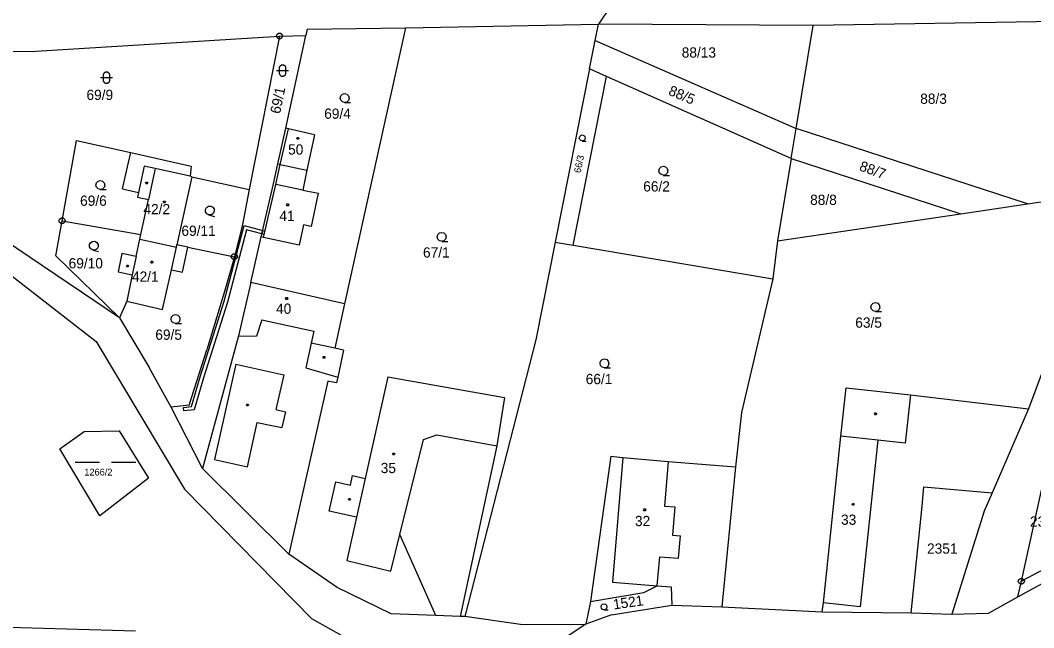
# Model space of a CAD drawing. Extents: x -852001 to -848657, y -1054973 to -1052182.
# Drawn here: x -850781 to -850612.8, y -1053430.4 to -1053329.6 of the extents above; entities that cross this region are included whole.
import ezdxf

# ---------------------------------------------------------------- set-up
doc = ezdxf.new("R2010")
doc.units = 0
for name, color, linetype in [('KN_BREMENA', 7, 'Continuous'), ('KN_HRANICE', 7, 'Continuous'), ('KN_KULTURY', 7, 'Continuous'), ('KN_MEZNIKY', 7, 'Continuous'), ('KN_PARCELY', 7, 'Continuous'), ('KN_SLUCKY', 7, 'Continuous'), ('KN_STAVEBNI', 7, 'Continuous')]:
    doc.layers.add(name, color=color, linetype=linetype)

# ---------------------------------------------------------------- blocks, each defined once
blk = doc.blocks.new('304')
blk.add_lwpolyline([(0, 0), (-0.38, 0.1), (-0.65, 0.37), (-0.75, 0.74), (-0.65, 1.11), (-0.38, 1.38), (-0.01, 1.48), (0.36, 1.38), (0.63, 1.11), (0.73, 0.73), (0.63, 0.35), (0.36, 0.08), (-0.02, -0.02), (0.98, -0.02)])
blk = doc.blocks.new('316')
for points in [[(-0.5, 1.5), (-0.4, 1.79), (-0.15, 1.97), (0.16, 1.97), (0.41, 1.79), (0.51, 1.5), (0.51, 0.5), (0.41, 0.21), (0.16, 0.03), (-0.15, 0.03), (-0.4, 0.21), (-0.5, 0.5), (-0.5, 1.5)], [(-1, 1), (0.27, 1), (1, 1)]]:
    blk.add_lwpolyline(points)
blk = doc.blocks.new('803')
for p, q in [((-7.5, 0), (-1.5, 0)), ((1.5, 0), (7.5, 0))]:
    blk.add_line(p, q)
blk = doc.blocks.new('402')
blk.add_lwpolyline([(0.09, 0.15), (0.18, 0), (0.09, -0.15), (-0.09, -0.15), (-0.18, 0), (-0.09, 0.15), (0.09, 0.15)])
blk = doc.blocks.new('105')
blk.add_line((-0.12, 0), (0.12, 0))
blk.add_lwpolyline([(0.15, 0.48), (0.4, 0.3), (0.5, 0.01), (0.4, -0.28), (0.15, -0.46), (-0.16, -0.46), (-0.41, -0.28), (-0.51, 0.01), (-0.41, 0.3), (-0.16, 0.48), (0.15, 0.48)])

msp = doc.modelspace()

# ---------------------------------------------------------------- linework, layer by layer
at = {"layer": 'KN_BREMENA'}
for p, q in [((-850743.82, -1053363.69), (-850740.72, -1053364.49)), ((-850740.72, -1053364.49), (-850740.85, -1053365.06))]:
    msp.add_line(p, q, dxfattribs=at)
msp.add_lwpolyline([(-850740.85, -1053365.06), (-850743.4, -1053364.41), (-850746.54, -1053376.39), (-850750.55, -1053388.95), (-850752.08, -1053394.24), (-850753.79, -1053394.45), (-850753.86, -1053393.86), (-850752.54, -1053393.7), (-850751.13, -1053388.77), (-850747.12, -1053376.23), (-850743.82, -1053363.69)], dxfattribs=at)
msp.add_lwpolyline([(-850740.72, -1053364.49), (-850740.39, -1053364.57), (-850740.52, -1053365.15), (-850740.85, -1053365.06)], close=True, dxfattribs=at)
at = {"layer": 'KN_HRANICE'}
for p, q in [((-850683.07, -1053327.37), (-850685.02, -1053330.25)), ((-850717.05, -1053330.88), (-850685.02, -1053330.25)), ((-850685.56, -1053333), (-850685.02, -1053330.25)), ((-850649.35, -1053330.52), (-850685.02, -1053330.25)), ((-850652.19, -1053347.57), (-850649.35, -1053330.52)), ((-850605.07, -1053329.74), (-850649.35, -1053330.52)), ((-850778.4, -1053334.78), (-850737.94, -1053332.24)), ((-850737.94, -1053332.24), (-850742.99, -1053357.7)), ((-850737.94, -1053332.24), (-850733.55, -1053332.18)), ((-850736.86, -1053347.53), (-850733.55, -1053332.18)), ((-850733.34, -1053331.11), (-850733.55, -1053332.18)), ((-850733.34, -1053331.11), (-850717.05, -1053330.88)), ((-850717.05, -1053330.88), (-850727.14, -1053376.69)), ((-850686.5, -1053337.71), (-850685.56, -1053333)), ((-850685.56, -1053333), (-850652.19, -1053347.57)), ((-850815.48, -1053335.08), (-850778.4, -1053334.78)), ((-850686.5, -1053337.71), (-850692.17, -1053366.45)), ((-850689.22, -1053366.95), (-850683.69, -1053338.94)), ((-850683.69, -1053338.94), (-850686.5, -1053337.71)), ((-850653.03, -1053352.56), (-850683.69, -1053338.94)), ((-850738.2, -1053353.47), (-850736.86, -1053347.53)), ((-850736.47, -1053347.62), (-850736.86, -1053347.53)), ((-850732.12, -1053348.62), (-850736.47, -1053347.62)), ((-850732.12, -1053348.62), (-850733.38, -1053354.52)), ((-850653.03, -1053352.56), (-850652.19, -1053347.57)), ((-850613.8, -1053360.1), (-850652.19, -1053347.57)), ((-850774.01, -1053362.91), (-850771.62, -1053349.55)), ((-850771.62, -1053349.55), (-850762.61, -1053351.58)), ((-850762.99, -1053353.25), (-850762.61, -1053351.58)), ((-850762.61, -1053351.58), (-850752.61, -1053353.83)), ((-850653.03, -1053352.56), (-850655.32, -1053366.23)), ((-850653.03, -1053352.56), (-850624.89, -1053361.75)), ((-850763.97, -1053357.61), (-850762.99, -1053353.25)), ((-850752.61, -1053353.83), (-850752.76, -1053355.52)), ((-850738.94, -1053356.76), (-850738.2, -1053353.47)), ((-850738.2, -1053353.47), (-850737.81, -1053353.56)), ((-850737.81, -1053353.56), (-850733.38, -1053354.52)), ((-850752.51, -1053355.58), (-850754.95, -1053366.89)), ((-850752.51, -1053355.58), (-850752.76, -1053355.52)), ((-850752.51, -1053355.58), (-850742.99, -1053357.7)), ((-850733.38, -1053354.52), (-850734.08, -1053357.8)), ((-850763.97, -1053357.61), (-850761.34, -1053358.18)), ((-850740.97, -1053365.57), (-850738.94, -1053356.76)), ((-850761.34, -1053358.18), (-850761.52, -1053358.99)), ((-850761.52, -1053358.99), (-850759.68, -1053359.39)), ((-850742.99, -1053357.7), (-850744.07, -1053363.49)), ((-850734.08, -1053357.8), (-850731.54, -1053358.34)), ((-850731.54, -1053358.34), (-850732.71, -1053363.82)), ((-850613.8, -1053360.1), (-850606.19, -1053358.98)), ((-850760.97, -1053365.18), (-850759.68, -1053359.39)), ((-850624.89, -1053361.75), (-850613.8, -1053360.1)), ((-850655.32, -1053366.23), (-850624.89, -1053361.75)), ((-850775.07, -1053368.7), (-850774.01, -1053362.91)), ((-850774.01, -1053362.91), (-850760.97, -1053365.18)), ((-850744.07, -1053363.49), (-850745.43, -1053368.86)), ((-850733.94, -1053363.56), (-850734.66, -1053366.93)), ((-850732.71, -1053363.82), (-850733.94, -1053363.56)), ((-850761.73, -1053368.82), (-850761.14, -1053365.96)), ((-850761.14, -1053365.96), (-850760.97, -1053365.18)), ((-850761.14, -1053365.96), (-850755.03, -1053367.28)), ((-850742.71, -1053373.12), (-850740.97, -1053365.57)), ((-850740.58, -1053365.66), (-850740.97, -1053365.57)), ((-850734.66, -1053366.93), (-850740.58, -1053365.66)), ((-850764.51, -1053379), (-850783.59, -1053366.1)), ((-850755.03, -1053367.28), (-850754.95, -1053366.89)), ((-850753.13, -1053367.26), (-850754.95, -1053366.89)), ((-850754.04, -1053371.43), (-850753.13, -1053367.26)), ((-850753.13, -1053367.26), (-850745.43, -1053368.86)), ((-850692.17, -1053366.45), (-850695.38, -1053382.66)), ((-850692.17, -1053366.45), (-850689.22, -1053366.95)), ((-850689.22, -1053366.95), (-850656.06, -1053372.51)), ((-850655.32, -1053366.23), (-850656.06, -1053372.51)), ((-850775.07, -1053368.7), (-850764.51, -1053379)), ((-850764.08, -1053368.33), (-850764.71, -1053371.37)), ((-850761.73, -1053368.82), (-850764.08, -1053368.33)), ((-850745.43, -1053368.86), (-850746.88, -1053374.1)), ((-850783.8, -1053370.9), (-850768.38, -1053382.92)), ((-850757.36, -1053377.59), (-850755.86, -1053371.06)), ((-850755.86, -1053371.06), (-850754.04, -1053371.43)), ((-850764.71, -1053371.37), (-850762.36, -1053371.85)), ((-850762.36, -1053371.85), (-850763.28, -1053376.26)), ((-850656.06, -1053372.51), (-850661.28, -1053394.73)), ((-850746.88, -1053374.1), (-850750, -1053384.28)), ((-850742.71, -1053373.12), (-850744.73, -1053381.99)), ((-850727.14, -1053376.69), (-850742.71, -1053373.12)), ((-850763.28, -1053376.26), (-850764.51, -1053379)), ((-850763.28, -1053376.26), (-850757.36, -1053377.59)), ((-850727.14, -1053376.69), (-850728.76, -1053384.05)), ((-850764.51, -1053379), (-850759.56, -1053387.26)), ((-850744.73, -1053381.99), (-850750.73, -1053404.02)), ((-850695.38, -1053382.66), (-850707.19, -1053428.56)), ((-850608.91, -1053381.35), (-850613.67, -1053394.11)), ((-850768.38, -1053382.92), (-850753.68, -1053407.41)), ((-850752.92, -1053393.49), (-850750, -1053384.28)), ((-850727.29, -1053384.37), (-850728.76, -1053384.05)), ((-850727.29, -1053384.37), (-850728.26, -1053388.82)), ((-850755.92, -1053393.81), (-850759.56, -1053387.26)), ((-850729.91, -1053389.48), (-850736.41, -1053418.2)), ((-850728.47, -1053389.8), (-850729.91, -1053389.48)), ((-850728.26, -1053388.82), (-850728.47, -1053389.8)), ((-850719.96, -1053388.76), (-850723.72, -1053405.65)), ((-850719.96, -1053388.76), (-850700.61, -1053392.2)), ((-850644.8, -1053398.62), (-850643.92, -1053390.61)), ((-850643.92, -1053390.61), (-850633.21, -1053391.79)), ((-850700.61, -1053392.2), (-850701.86, -1053400.23)), ((-850633.21, -1053391.79), (-850613.67, -1053394.11)), ((-850752.92, -1053393.49), (-850755.92, -1053393.81)), ((-850750.73, -1053404.02), (-850755.92, -1053393.81)), ((-850613.67, -1053394.11), (-850619.67, -1053408.02)), ((-850661.28, -1053394.73), (-850662.28, -1053403.7)), ((-850774.4, -1053400.72), (-850770.36, -1053397.87)), ((-850770.36, -1053397.87), (-850764.52, -1053397.77)), ((-850764.52, -1053397.77), (-850759.66, -1053405.62)), ((-850647.64, -1053426.28), (-850644.8, -1053398.62)), ((-850767.78, -1053411.85), (-850774.4, -1053400.72)), ((-850701.86, -1053400.23), (-850707.94, -1053428.53)), ((-850614.83, -1053422.71), (-850610.11, -1053401.34)), ((-850682.94, -1053401.97), (-850686.34, -1053426.05)), ((-850682.94, -1053401.97), (-850680.99, -1053402.15)), ((-850680.99, -1053402.15), (-850673.43, -1053402.82)), ((-850673.43, -1053402.82), (-850662.28, -1053403.7)), ((-850736.41, -1053418.2), (-850750.73, -1053404.02)), ((-850662.28, -1053403.7), (-850664.55, -1053426.95)), ((-850759.66, -1053405.62), (-850767.78, -1053411.85)), ((-850729.69, -1053411.08), (-850728.61, -1053406.2)), ((-850728.61, -1053406.2), (-850726.16, -1053406.74)), ((-850726.16, -1053406.74), (-850725.82, -1053405.18)), ((-850725.82, -1053405.18), (-850723.72, -1053405.65)), ((-850732.58, -1053428.94), (-850753.68, -1053407.41)), ((-850631.28, -1053410.23), (-850631.01, -1053407.05)), ((-850631.01, -1053407.05), (-850619.67, -1053408.02)), ((-850619.67, -1053408.02), (-850621, -1053411.06)), ((-850725.15, -1053412.09), (-850729.69, -1053411.08)), ((-850633.09, -1053427.94), (-850631.28, -1053410.23)), ((-850621, -1053411.06), (-850626.39, -1053428.15)), ((-850725.15, -1053412.09), (-850726.75, -1053419.27)), ((-850599.75, -1053414.73), (-850614.83, -1053422.71)), ((-850719.44, -1053421.05), (-850717.98, -1053414.96)), ((-850712, -1053428.38), (-850717.98, -1053414.96)), ((-850615.4, -1053425.29), (-850599.94, -1053416.73)), ((-850728.38, -1053423.75), (-850736.41, -1053418.2)), ((-850726.75, -1053419.27), (-850719.44, -1053421.05)), ((-850615.4, -1053425.29), (-850614.83, -1053422.71)), ((-850719.41, -1053428.11), (-850728.38, -1053423.75)), ((-850686.34, -1053426.05), (-850677.49, -1053424.55)), ((-850677.49, -1053424.55), (-850675.24, -1053423.48)), ((-850675.24, -1053423.48), (-850672.94, -1053423.65)), ((-850672.94, -1053423.65), (-850672.81, -1053426.68)), ((-850686.34, -1053426.05), (-850687.09, -1053429.83)), ((-850647.86, -1053427.79), (-850647.64, -1053426.28)), ((-850620.26, -1053427.98), (-850615.4, -1053425.29)), ((-850712, -1053428.38), (-850719.41, -1053428.11)), ((-850682.84, -1053428.25), (-850687.09, -1053429.83)), ((-850682.84, -1053428.25), (-850672.81, -1053426.68)), ((-850672.81, -1053426.68), (-850664.55, -1053426.95)), ((-850664.55, -1053426.95), (-850647.86, -1053427.79)), ((-850647.86, -1053427.79), (-850633.09, -1053427.94)), ((-850633.09, -1053427.94), (-850626.39, -1053428.15)), ((-850626.39, -1053428.15), (-850620.26, -1053427.98)), ((-850800.29, -1053429.81), (-850761.82, -1053430.94)), ((-850721.08, -1053435.35), (-850732.58, -1053428.94)), ((-850707.94, -1053428.53), (-850712, -1053428.38)), ((-850707.19, -1053428.56), (-850707.94, -1053428.53)), ((-850697.93, -1053429.89), (-850707.19, -1053428.56)), ((-850697.93, -1053429.89), (-850687.09, -1053429.83)), ((-850687.09, -1053429.83), (-850693.44, -1053434))]:
    msp.add_line(p, q, dxfattribs=at)
at = {"layer": 'KN_SLUCKY'}
for p, q in [((-850737.81, -1053353.56), (-850736.47, -1053347.62)), ((-850760.4, -1053353.83), (-850761.34, -1053358.18)), ((-850758.56, -1053354.23), (-850760.4, -1053353.83)), ((-850758.56, -1053354.23), (-850759.68, -1053359.39)), ((-850752.76, -1053355.52), (-850758.56, -1053354.23)), ((-850738.55, -1053356.85), (-850737.81, -1053353.56)), ((-850740.58, -1053365.66), (-850738.55, -1053356.85)), ((-850734.08, -1053357.8), (-850738.55, -1053356.85)), ((-850755.86, -1053371.06), (-850755.03, -1053367.28)), ((-850761.73, -1053368.82), (-850762.36, -1053371.85)), ((-850740.86, -1053379.33), (-850741.78, -1053382.03)), ((-850740.86, -1053379.33), (-850732.23, -1053381.21)), ((-850744.73, -1053381.99), (-850741.78, -1053382.03)), ((-850732.23, -1053381.21), (-850732.66, -1053383.2)), ((-850732.66, -1053383.2), (-850733.55, -1053387.28)), ((-850728.76, -1053384.05), (-850732.66, -1053383.2)), ((-850745.21, -1053386.71), (-850748.7, -1053402.5)), ((-850745.21, -1053386.71), (-850737.24, -1053388.44)), ((-850733.55, -1053387.28), (-850728.26, -1053388.82)), ((-850737.24, -1053388.44), (-850738.57, -1053394.19)), ((-850633.21, -1053391.79), (-850634.1, -1053399.81)), ((-850738.57, -1053394.19), (-850736.94, -1053394.57)), ((-850736.94, -1053394.57), (-850737.55, -1053397.22)), ((-850743.26, -1053403.71), (-850741.63, -1053396.36)), ((-850741.63, -1053396.36), (-850739.2, -1053396.84)), ((-850739.2, -1053396.84), (-850737.55, -1053397.22)), ((-850717.98, -1053414.96), (-850714.06, -1053399.19)), ((-850714.06, -1053399.19), (-850711.85, -1053398.4)), ((-850711.85, -1053398.4), (-850701.86, -1053400.23)), ((-850638.67, -1053399.32), (-850644.8, -1053398.62)), ((-850638.67, -1053399.32), (-850641.6, -1053426.95)), ((-850634.1, -1053399.81), (-850638.67, -1053399.32)), ((-850748.7, -1053402.5), (-850743.26, -1053403.71)), ((-850680.99, -1053402.15), (-850682.67, -1053422.88)), ((-850673.43, -1053402.82), (-850674.07, -1053410.23)), ((-850723.72, -1053405.65), (-850725.15, -1053412.09)), ((-850674.07, -1053410.23), (-850672.33, -1053410.38)), ((-850672.33, -1053410.38), (-850672.74, -1053415.05)), ((-850672.74, -1053415.05), (-850671.4, -1053415.17)), ((-850671.72, -1053418.85), (-850671.4, -1053415.17)), ((-850675.24, -1053423.48), (-850674.85, -1053418.65)), ((-850674.85, -1053418.65), (-850671.72, -1053418.85)), ((-850682.67, -1053422.88), (-850675.24, -1053423.48)), ((-850641.6, -1053426.95), (-850647.64, -1053426.28))]:
    msp.add_line(p, q, dxfattribs=at)
at = {"layer": 'KN_STAVEBNI'}
for p, q in [((-850737.81, -1053353.56), (-850736.47, -1053347.62)), ((-850732.12, -1053348.62), (-850736.47, -1053347.62)), ((-850732.12, -1053348.62), (-850733.38, -1053354.52)), ((-850758.56, -1053354.23), (-850759.68, -1053359.39)), ((-850752.76, -1053355.52), (-850758.56, -1053354.23)), ((-850737.81, -1053353.56), (-850733.38, -1053354.52)), ((-850752.51, -1053355.58), (-850754.95, -1053366.89)), ((-850752.51, -1053355.58), (-850752.76, -1053355.52)), ((-850740.58, -1053365.66), (-850738.55, -1053356.85)), ((-850734.08, -1053357.8), (-850738.55, -1053356.85)), ((-850734.08, -1053357.8), (-850731.54, -1053358.34)), ((-850731.54, -1053358.34), (-850732.71, -1053363.82)), ((-850760.97, -1053365.18), (-850759.68, -1053359.39)), ((-850733.94, -1053363.56), (-850734.66, -1053366.93)), ((-850732.71, -1053363.82), (-850733.94, -1053363.56)), ((-850761.73, -1053368.82), (-850761.14, -1053365.96)), ((-850761.14, -1053365.96), (-850760.97, -1053365.18)), ((-850761.14, -1053365.96), (-850755.03, -1053367.28)), ((-850761.14, -1053365.96), (-850755.03, -1053367.28)), ((-850734.66, -1053366.93), (-850740.58, -1053365.66)), ((-850755.86, -1053371.06), (-850755.03, -1053367.28)), ((-850755.03, -1053367.28), (-850754.95, -1053366.89)), ((-850761.73, -1053368.82), (-850762.36, -1053371.85)), ((-850757.36, -1053377.59), (-850755.86, -1053371.06)), ((-850762.36, -1053371.85), (-850763.28, -1053376.26)), ((-850742.71, -1053373.12), (-850744.73, -1053381.99)), ((-850727.14, -1053376.69), (-850742.71, -1053373.12)), ((-850763.28, -1053376.26), (-850757.36, -1053377.59)), ((-850727.14, -1053376.69), (-850728.76, -1053384.05)), ((-850740.86, -1053379.33), (-850741.78, -1053382.03)), ((-850740.86, -1053379.33), (-850732.23, -1053381.21)), ((-850744.73, -1053381.99), (-850741.78, -1053382.03)), ((-850732.23, -1053381.21), (-850732.66, -1053383.2)), ((-850728.76, -1053384.05), (-850732.66, -1053383.2)), ((-850719.96, -1053388.76), (-850723.72, -1053405.65)), ((-850719.96, -1053388.76), (-850700.61, -1053392.2)), ((-850700.61, -1053392.2), (-850701.86, -1053400.23)), ((-850717.98, -1053414.96), (-850714.06, -1053399.19)), ((-850714.06, -1053399.19), (-850711.85, -1053398.4)), ((-850711.85, -1053398.4), (-850701.86, -1053400.23)), ((-850647.64, -1053426.28), (-850644.8, -1053398.62)), ((-850638.67, -1053399.32), (-850644.8, -1053398.62)), ((-850638.67, -1053399.32), (-850641.6, -1053426.95)), ((-850680.99, -1053402.15), (-850682.67, -1053422.88)), ((-850680.99, -1053402.15), (-850673.43, -1053402.82)), ((-850673.43, -1053402.82), (-850674.07, -1053410.23)), ((-850723.72, -1053405.65), (-850725.15, -1053412.09)), ((-850674.07, -1053410.23), (-850672.33, -1053410.38)), ((-850672.33, -1053410.38), (-850672.74, -1053415.05)), ((-850725.15, -1053412.09), (-850726.75, -1053419.27)), ((-850719.44, -1053421.05), (-850717.98, -1053414.96)), ((-850672.74, -1053415.05), (-850671.4, -1053415.17)), ((-850671.72, -1053418.85), (-850671.4, -1053415.17)), ((-850726.75, -1053419.27), (-850719.44, -1053421.05)), ((-850675.24, -1053423.48), (-850674.85, -1053418.65)), ((-850674.85, -1053418.65), (-850671.72, -1053418.85)), ((-850682.67, -1053422.88), (-850675.24, -1053423.48)), ((-850641.6, -1053426.95), (-850647.64, -1053426.28))]:
    msp.add_line(p, q, dxfattribs=at)

# ---------------------------------------------------------------- block references
at = {"layer": 'KN_KULTURY'}
for name, p in [('316', (-850737.43, -1053338.97)), ('316', (-850766.65, -1053340.15)), ('304', (-850727.12, -1053343.27)), ('402', (-850734.89, -1053349.21)), ('304', (-850674.22, -1053355.34)), ('304', (-850767.67, -1053357.71)), ('402', (-850759.98, -1053356.64)), ('402', (-850757.04, -1053359.79)), ('402', (-850736.58, -1053360.24)), ('304', (-850711, -1053366.3)), ('402', (-850763.15, -1053370.39)), ('402', (-850759.13, -1053369.76)), ('402', (-850736.74, -1053375.78)), ('304', (-850639.03, -1053377.94)), ('304', (-850755.19, -1053379.94)), ('402', (-850730.54, -1053385.54)), ('304', (-850684, -1053387.3)), ('402', (-850743.25, -1053393.45)), ('402', (-850639.02, -1053394.93)), ('402', (-850718.98, -1053401.6)), ('402', (-850726.33, -1053409.11)), ('402', (-850677.33, -1053410.86)), ('402', (-850642.75, -1053409.95))]:
    msp.add_blockref(name, p, dxfattribs=at)
at = {"layer": 'KN_KULTURY', "xscale": 0.67, "yscale": 0.67}
for name, p in [('304', (-850687.68, -1053349.65)), ('803', (-850766.81, -1053402.95)), ('304', (-850684.08, -1053427.44))]:
    msp.add_blockref(name, p, dxfattribs=at)
at = {"layer": 'KN_KULTURY', "rotation": -13.589717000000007}
for p in [(-850749.67, -1053361.91), (-850749.67, -1053361.91), (-850768.9, -1053367.74), (-850768.9, -1053367.74)]:
    msp.add_blockref('304', p, dxfattribs=at)
at = {"layer": 'KN_MEZNIKY'}
for p in [(-850737.94, -1053332.24), (-850774.01, -1053362.91), (-850745.43, -1053368.86), (-850614.83, -1053422.71)]:
    msp.add_blockref('105', p, dxfattribs=at)

# ---------------------------------------------------------------- texts
at = {"layer": 'KN_PARCELY'}
for s, height, p in [('88/13', 1.7, (-850671.19, -1053335.82)), ('69/9', 1.7, (-850769.97, -1053342.85)), ('88/3', 1.7, (-850631.61, -1053343.49)), ('69/4', 1.7, (-850730.52, -1053345.97)), ('50', 1.7, (-850736.51, -1053351.91)), ('66/2', 1.7, (-850677.58, -1053358.04)), ('69/6', 1.7, (-850771.03, -1053360.41)), ('88/8', 1.7, (-850649.88, -1053360.26)), ('42/2', 1.7, (-850760.52, -1053361.81)), ('41', 1.7, (-850737.96, -1053362.94)), ('69/11', 1.7, (-850754.21, -1053365.4)), ('67/1', 1.7, (-850714.12, -1053369)), ('69/10', 1.7, (-850772.93, -1053370.79)), ('42/1', 1.7, (-850762.42, -1053373.01)), ('40', 1.7, (-850738.51, -1053378.33)), ('63/5', 1.7, (-850642.39, -1053380.64)), ('69/5', 1.7, (-850758.55, -1053382.64)), ('66/1', 1.7, (-850687.12, -1053390)), ('35', 1.7, (-850721.14, -1053404.76)), ('1266/2', 1.14, (-850770.32, -1053405.16)), ('32', 1.7, (-850678.95, -1053413.56)), ('33', 1.7, (-850644.75, -1053413.34)), ('2352', 1.7, (-850613.4, -1053413.65)), ('2351', 1.7, (-850630.48, -1053418.13))]:
    msp.add_text(s, height=height, dxfattribs=at).set_placement(p)
for s, height, rotation, p in [('88/5', 1.7, 337.128, (-850673.54, -1053341.94)), ('69/1', 1.7, 78.495, (-850737.84, -1053345.24)), ('66/3', 1.14, 78.266, (-850687.98, -1053355.04)), ('88/7', 1.7, 340.05, (-850641.85, -1053354.5)), ('1521', 1.7, 8.079, (-850682.46, -1053427.4))]:
    msp.add_text(s, height=height, rotation=rotation, dxfattribs=at).set_placement(p)

doc.saveas('drawing.dxf')
